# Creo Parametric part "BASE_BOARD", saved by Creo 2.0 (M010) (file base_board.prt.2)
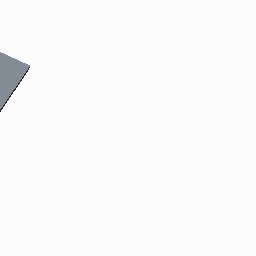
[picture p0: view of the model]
Units: Inch lbm Second (Pro/E Default); INCH, POUND, SECS

Created from: INLBS_PART_SOLID.PRT

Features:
  1. datum plane "RIGHT"
  2. datum plane "TOP"
  3. datum plane "FRONT"
  4. coordinate system
  5. sketch "Sketch 1"
  6. extrusion "Extrude 1", "Sketch 1"

Surfaces: 9 plane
